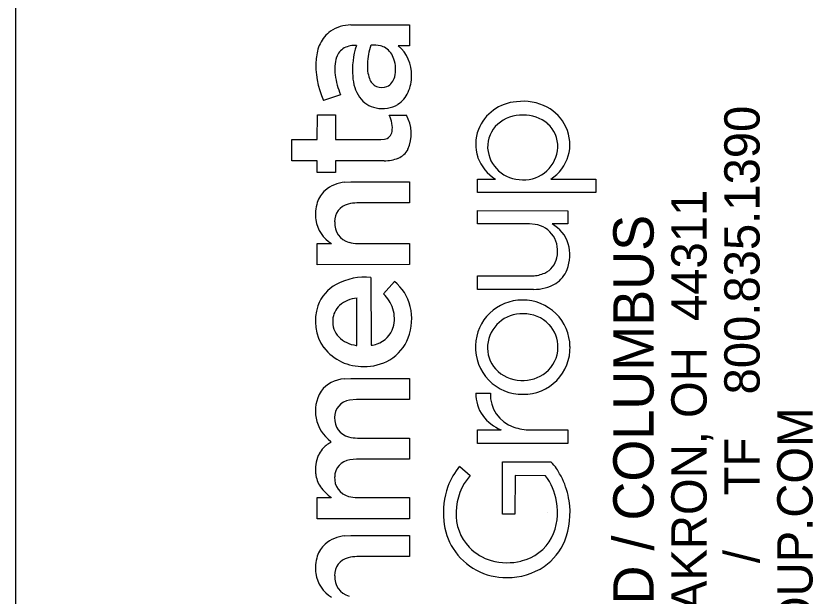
# Model space of a CAD drawing. Extents: x -6.7 to 34, y -1.6 to 22.
# Drawn here: x 32 to 33.125, y 3.882 to 4.702 of the extents above; entities that cross this region are included whole.
import ezdxf

# ---------------------------------------------------------------- set-up
doc = ezdxf.new("R2010")
doc.units = 0
doc.layers.add('SH_Border', color=7, linetype='Continuous')
doc.layers.add('SH_Data', color=7, linetype='Continuous')

msp = doc.modelspace()

# ---------------------------------------------------------------- linework, layer by layer
at = {"layer": 'SH_Border'}
msp.add_line((32, 0.5), (32, 21.5), dxfattribs=at)
at = {"layer": 'SH_Data'}
for p, q in [((32.4727, 4.689), (32.5555, 4.6892)), ((32.5555, 4.6892), (32.5557, 4.6596)), ((32.5557, 4.6596), (32.5397, 4.6596)), ((32.4582, 4.5904), (32.4343, 4.5823)), ((32.4254, 4.527), (32.4255, 4.5621)), ((32.4255, 4.5621), (32.4511, 4.5621)), ((32.4511, 4.5621), (32.4512, 4.527)), ((32.527, 4.5616), (32.5511, 4.5616)), ((32.3896, 4.4972), (32.3896, 4.527)), ((32.3896, 4.527), (32.4254, 4.527)), ((32.4512, 4.527), (32.515, 4.527)), ((32.515, 4.527), (32.52, 4.5275)), ((32.4254, 4.4972), (32.3896, 4.4972)), ((32.4254, 4.4807), (32.4254, 4.4972)), ((32.5197, 4.4972), (32.4511, 4.4972)), ((32.4511, 4.4972), (32.4511, 4.4807)), ((32.4511, 4.4807), (32.4254, 4.4807)), ((32.4644, 4.4669), (32.4729, 4.4673)), ((32.4729, 4.4673), (32.5557, 4.4673)), ((32.5557, 4.4673), (32.5557, 4.4375)), ((32.6515, 4.4521), (32.6515, 4.4711)), ((32.6515, 4.4711), (32.6771, 4.4711)), ((32.7549, 4.4713), (32.8186, 4.4711)), ((32.8186, 4.4711), (32.8184, 4.4521)), ((32.8184, 4.4521), (32.6515, 4.4521)), ((32.5557, 4.4375), (32.4814, 4.4375)), ((32.6515, 4.408), (32.6515, 4.4267)), ((32.6515, 4.4267), (32.7791, 4.4266)), ((32.7791, 4.4266), (32.7791, 4.408)), ((32.7249, 4.408), (32.6515, 4.408)), ((32.7328, 4.4073), (32.7249, 4.408)), ((32.7791, 4.408), (32.7569, 4.408)), ((32.4254, 4.3503), (32.4254, 4.3802)), ((32.4254, 4.3802), (32.4455, 4.3802)), ((32.4822, 4.3802), (32.5557, 4.3802)), ((32.5557, 4.3802), (32.5557, 4.3504)), ((32.5557, 4.3504), (32.4254, 4.3503)), ((32.5011, 4.3321), (32.5012, 4.2366)), ((32.6515, 4.3344), (32.7291, 4.3345)), ((32.6517, 4.3154), (32.6515, 4.3344)), ((32.5188, 4.3093), (32.5342, 4.3266)), ((32.7307, 4.3154), (32.6517, 4.3154)), ((32.4814, 4.2364), (32.4814, 4.303)), ((32.4802, 4.2363), (32.4814, 4.2364)), ((32.4633, 4.1891), (32.4726, 4.1897)), ((32.4726, 4.1897), (32.5556, 4.1897)), ((32.5556, 4.1897), (32.5557, 4.1598)), ((32.6493, 4.1691), (32.6698, 4.1691)), ((32.4806, 4.1598), (32.471, 4.1588)), ((32.5557, 4.1598), (32.4806, 4.1598)), ((32.6515, 4.098), (32.6515, 4.117)), ((32.6515, 4.117), (32.6848, 4.117)), ((32.726, 4.117), (32.7791, 4.117)), ((32.7791, 4.117), (32.779, 4.098)), ((32.4444, 4.0992), (32.4446, 4.1007)), ((32.4822, 4.1055), (32.5557, 4.1055)), ((32.5557, 4.1055), (32.5557, 4.0757)), ((32.779, 4.098), (32.6515, 4.098)), ((32.4809, 4.0757), (32.4714, 4.0747)), ((32.5557, 4.0757), (32.4809, 4.0757)), ((32.6264, 4.0655), (32.6411, 4.0524)), ((32.6868, 4.0718), (32.7552, 4.0719)), ((32.6868, 3.9978), (32.6868, 4.0718)), ((32.7045, 4.0524), (32.7043, 3.9978)), ((32.7474, 4.0523), (32.7045, 4.0524)), ((32.4254, 3.9915), (32.4254, 4.0214)), ((32.4254, 4.0214), (32.4451, 4.0214)), ((32.4821, 4.0214), (32.5557, 4.0214)), ((32.5557, 4.0214), (32.5557, 3.9916)), ((32.7043, 3.9978), (32.6868, 3.9978)), ((32.75, 4), (32.75, 4)), ((32.5557, 3.9916), (32.4254, 3.9915)), ((32.4644, 3.9674), (32.4729, 3.9678)), ((32.4729, 3.9678), (32.5557, 3.9678)), ((32.5557, 3.9678), (32.5557, 3.938)), ((32.5557, 3.938), (32.4814, 3.938))]:
    msp.add_line(p, q, dxfattribs=at)
for points in [[(32.4727, 4.689), (32.5555, 4.6892), (32.5557, 4.6596)], [(32.5557, 4.6596), (32.5397, 4.6596)], [(32.4582, 4.5904), (32.4343, 4.5823)], [(32.5197, 4.4972), (32.4511, 4.4972), (32.4511, 4.4807), (32.4254, 4.4807), (32.4254, 4.4972), (32.3896, 4.4972), (32.3896, 4.527), (32.4254, 4.527), (32.4255, 4.5621), (32.4511, 4.5621), (32.4512, 4.527), (32.515, 4.527), (32.52, 4.5275)], [(32.527, 4.5616), (32.5511, 4.5616)], [(32.4644, 4.4669), (32.4729, 4.4673), (32.5557, 4.4673), (32.5557, 4.4375), (32.4814, 4.4375)], [(32.7549, 4.4713), (32.8186, 4.4711), (32.8184, 4.4521), (32.6515, 4.4521)], [(32.6515, 4.4521), (32.6515, 4.4711), (32.6771, 4.4711)], [(32.7328, 4.4073), (32.7249, 4.408), (32.6515, 4.408), (32.6515, 4.4267), (32.7791, 4.4266), (32.7791, 4.408), (32.7569, 4.408)], [(32.4254, 4.3503), (32.4254, 4.3802), (32.4455, 4.3802)], [(32.4822, 4.3802), (32.5557, 4.3802), (32.5557, 4.3504), (32.4254, 4.3503)], [(32.5011, 4.3321), (32.5012, 4.2366)], [(32.7307, 4.3154), (32.6517, 4.3154), (32.6515, 4.3344), (32.7291, 4.3345)], [(32.5188, 4.3093), (32.5342, 4.3266)], [(32.4802, 4.2363), (32.4814, 4.2364), (32.4814, 4.303)], [(32.4633, 4.1891), (32.4726, 4.1897), (32.5556, 4.1897), (32.5557, 4.1598), (32.4806, 4.1598), (32.471, 4.1588)], [(32.6493, 4.1691), (32.6698, 4.1691)], [(32.6515, 4.098), (32.6515, 4.117), (32.6848, 4.117)], [(32.726, 4.117), (32.7791, 4.117), (32.779, 4.098), (32.6515, 4.098)], [(32.4444, 4.0992), (32.4446, 4.1007)], [(32.4822, 4.1055), (32.5557, 4.1055), (32.5557, 4.0757), (32.4809, 4.0757), (32.4714, 4.0747)], [(32.6264, 4.0655), (32.6411, 4.0524)], [(32.7474, 4.0523), (32.7045, 4.0524), (32.7043, 3.9978), (32.6868, 3.9978), (32.6868, 4.0718), (32.7552, 4.0719)], [(32.4254, 3.9915), (32.4254, 4.0214), (32.4451, 4.0214)], [(32.4821, 4.0214), (32.5557, 4.0214), (32.5557, 3.9916), (32.4254, 3.9915)], [(32.4644, 3.9674), (32.4729, 3.9678), (32.5557, 3.9678), (32.5557, 3.938), (32.4814, 3.938)]]:
    msp.add_lwpolyline(points, dxfattribs=at)
for centre, radius, start, end in [((32.4745, 4.6326), 0.0565, 91.8942, 122.6317), ((32.4745, 4.6326), 0.0565, 91.8942, 122.6317), ((32.4685, 4.6447), 0.043, 124.537, 155.6594), ((32.4685, 4.6447), 0.043, 124.537, 155.6594), ((32.4882, 4.6361), 0.0646, 155.9764, 175.3149), ((32.4882, 4.6361), 0.0646, 155.9764, 175.3149), ((32.4779, 4.6278), 0.0321, 85.3802, 116.6222), ((32.4779, 4.6278), 0.0321, 85.3802, 116.6222), ((32.5879, 4.6251), 0.1129, 162.0821, 184.5285), ((32.5879, 4.6251), 0.1129, 162.0821, 184.5285), ((32.5801, 4.6313), 0.0841, 159.8366, 178.0362), ((32.5801, 4.6313), 0.0841, 159.8366, 178.0362), ((32.5051, 4.6074), 0.053, 79.6696, 94.2322), ((32.5051, 4.6074), 0.053, 79.6696, 94.2322), ((32.5089, 4.6364), 0.0238, 56.8913, 76.2149), ((32.5089, 4.6364), 0.0238, 56.8913, 76.2149), ((32.5055, 4.6191), 0.0529, 358.0746, 49.762), ((32.5055, 4.6191), 0.0529, 358.0746, 49.762), ((32.4753, 4.6356), 0.024, 119.4252, 161.6629), ((32.4753, 4.6356), 0.024, 119.4252, 161.6629), ((32.5052, 4.6318), 0.0297, 17.5984, 55.7282), ((32.5052, 4.6318), 0.0297, 17.5984, 55.7282), ((32.5364, 4.6308), 0.113, 174.6101, 205.3899), ((32.5364, 4.6308), 0.113, 174.6101, 205.3899), ((32.5076, 4.6265), 0.0576, 163.1369, 188.1675), ((32.5076, 4.6265), 0.0576, 163.1369, 188.1675), ((32.4916, 4.6264), 0.0443, 345.9408, 18.9919), ((32.4916, 4.6264), 0.0443, 345.9408, 18.9919), ((32.5466, 4.6303), 0.0506, 175.5903, 199.8857), ((32.5466, 4.6303), 0.0506, 175.5903, 199.8857), ((32.5473, 4.6297), 0.0973, 186.7598, 203.7981), ((32.5473, 4.6297), 0.0973, 186.7598, 203.7981), ((32.5328, 4.6187), 0.0575, 182.5676, 213.7144), ((32.5328, 4.6187), 0.0575, 182.5676, 213.7144), ((32.5164, 4.6189), 0.0184, 198.2844, 293.3081), ((32.5164, 4.6189), 0.0184, 198.2844, 293.3081), ((32.5152, 4.6199), 0.0199, 295.2883, 347.4639), ((32.5152, 4.6199), 0.0199, 295.2883, 347.4639), ((32.5019, 4.6168), 0.0566, 336.016, 0.5951), ((32.5019, 4.6168), 0.0566, 336.016, 0.5951), ((32.5175, 4.6097), 0.0394, 303.4436, 336.18), ((32.5175, 4.6097), 0.0394, 303.4436, 336.18), ((32.5149, 4.6078), 0.0366, 215.0668, 259.8133), ((32.5149, 4.6078), 0.0366, 215.0668, 259.8133), ((32.7108, 4.5182), 0.0624, 93.9866, 158.3119), ((32.7108, 4.5182), 0.0624, 93.9866, 158.3119), ((32.7156, 4.5065), 0.0746, 62.6889, 97.0135), ((32.7156, 4.5065), 0.0746, 62.6889, 97.0135), ((32.5175, 4.6131), 0.0423, 257.5256, 300.882), ((32.5175, 4.6131), 0.0423, 257.5256, 300.882), ((32.7212, 4.5191), 0.0608, 25.0657, 61.9602), ((32.7212, 4.5191), 0.0608, 25.0657, 61.9602), ((32.4863, 4.542), 0.0452, 10.1545, 25.723), ((32.4863, 4.542), 0.0452, 10.1545, 25.723), ((32.503, 4.5351), 0.0549, 336.589, 28.8991), ((32.503, 4.5351), 0.0549, 336.589, 28.8991), ((32.7138, 4.5102), 0.0513, 87.8965, 131.1812), ((32.7138, 4.5102), 0.0513, 87.8965, 131.1812), ((32.7175, 4.5102), 0.0513, 49.9089, 92.0363), ((32.7175, 4.5102), 0.0513, 49.9089, 92.0363), ((32.4957, 4.5436), 0.0356, 351.914, 10.2059), ((32.4957, 4.5436), 0.0356, 351.914, 10.2059), ((32.7092, 4.5167), 0.0434, 132.3289, 182.0949), ((32.7092, 4.5167), 0.0434, 132.3289, 182.0949), ((32.7215, 4.5173), 0.0433, 358.0487, 47.9447), ((32.7215, 4.5173), 0.0433, 358.0487, 47.9447), ((32.5184, 4.54), 0.0126, 277.6142, 353.7918), ((32.5184, 4.54), 0.0126, 277.6142, 353.7918), ((32.707, 4.5202), 0.0581, 158.656, 198.171), ((32.707, 4.5202), 0.0581, 158.656, 198.171), ((32.7245, 4.52), 0.0574, 301.9776, 25.6418), ((32.7245, 4.52), 0.0574, 301.9776, 25.6418), ((32.5291, 4.5261), 0.0275, 292.6889, 332.0598), ((32.5291, 4.5261), 0.0275, 292.6889, 332.0598), ((32.7135, 4.5181), 0.0478, 183.5974, 271.7045), ((32.7135, 4.5181), 0.0478, 183.5974, 271.7045), ((32.7172, 4.518), 0.0477, 267.3149, 357.4019), ((32.7172, 4.518), 0.0477, 267.3149, 357.4019), ((32.5209, 4.5486), 0.0514, 268.6727, 291.5235), ((32.5209, 4.5486), 0.0514, 268.6727, 291.5235), ((32.7103, 4.5243), 0.0627, 200.8399, 238.0162), ((32.7103, 4.5243), 0.0627, 200.8399, 238.0162), ((32.4687, 4.4172), 0.0499, 94.9706, 130.2248), ((32.4687, 4.4172), 0.0499, 94.9706, 130.2248), ((32.4635, 4.4255), 0.0402, 132.2238, 161.6823), ((32.4635, 4.4255), 0.0402, 132.2238, 161.6823), ((32.4787, 4.4211), 0.056, 162.274, 187.7917), ((32.4787, 4.4211), 0.056, 162.274, 187.7917), ((32.4748, 4.4116), 0.025, 103.6868, 182.214), ((32.4748, 4.4116), 0.025, 103.6868, 182.214), ((32.4811, 4.3915), 0.046, 89.6051, 105.3303), ((32.4811, 4.3915), 0.046, 89.6051, 105.3303), ((32.4703, 4.4209), 0.0476, 188.9646, 238.6987), ((32.4703, 4.4209), 0.0476, 188.9646, 238.6987), ((32.4774, 4.4085), 0.0276, 175.5844, 255.1382), ((32.4774, 4.4085), 0.0276, 175.5844, 255.1382), ((32.7271, 4.37), 0.0377, 33.5008, 81.3295), ((32.7271, 4.37), 0.0377, 33.5008, 81.3295), ((32.7324, 4.3648), 0.0496, 17.6221, 60.3897), ((32.7324, 4.3648), 0.0496, 17.6221, 60.3897), ((32.7241, 4.3695), 0.0405, 346.5618, 31.7539), ((32.7241, 4.3695), 0.0405, 346.5618, 31.7539), ((32.4818, 4.4224), 0.0421, 254.0891, 270.5284), ((32.4818, 4.4224), 0.0421, 254.0891, 270.5284), ((32.7234, 4.3641), 0.0584, 339.162, 15.6148), ((32.7234, 4.3641), 0.0584, 339.162, 15.6148), ((32.7337, 4.3662), 0.0304, 294.6321, 348.4863), ((32.7337, 4.3662), 0.0304, 294.6321, 348.4863), ((32.739, 4.359), 0.042, 303.1039, 338.1561), ((32.739, 4.359), 0.042, 303.1039, 338.1561), ((32.4918, 4.2487), 0.0839, 83.6212, 118.2845), ((32.4918, 4.2487), 0.0839, 83.6212, 118.2845), ((32.7275, 4.3808), 0.0463, 271.952, 294.0894), ((32.7275, 4.3808), 0.0463, 271.952, 294.0894), ((32.4789, 4.2737), 0.0558, 118.8294, 160.6224), ((32.4789, 4.2737), 0.0558, 118.8294, 160.6224), ((32.494, 4.2763), 0.0644, 13.5328, 51.3627), ((32.494, 4.2763), 0.0644, 13.5328, 51.3627), ((32.7321, 4.3726), 0.0571, 268.627, 301.4778), ((32.7321, 4.3726), 0.0571, 268.627, 301.4778), ((32.4803, 4.2702), 0.0549, 19.0387, 45.4432), ((32.4803, 4.2702), 0.0549, 19.0387, 45.4432), ((32.4844, 4.2607), 0.0424, 94.0131, 130.8806), ((32.4844, 4.2607), 0.0424, 94.0131, 130.8806), ((32.7143, 4.2348), 0.0655, 89.4821, 178.7775), ((32.7143, 4.2348), 0.0655, 89.4821, 178.7775), ((32.7158, 4.2341), 0.0662, 0.4227, 90.7613), ((32.7158, 4.2341), 0.0662, 0.4227, 90.7613), ((32.487, 4.2707), 0.0644, 160.5214, 215.7815), ((32.487, 4.2707), 0.0644, 160.5214, 215.7815), ((32.477, 4.2709), 0.0298, 132.9855, 177.1802), ((32.477, 4.2709), 0.0298, 132.9855, 177.1802), ((32.4872, 4.2743), 0.047, 344.6072, 17.0067), ((32.4872, 4.2743), 0.047, 344.6072, 17.0067), ((32.4829, 4.2738), 0.0758, 339.3543, 13.3771), ((32.4829, 4.2738), 0.0758, 339.3543, 13.3771), ((32.714, 4.2324), 0.0485, 87.6883, 175.017), ((32.714, 4.2324), 0.0485, 87.6883, 175.017), ((32.7166, 4.2304), 0.0505, 44.912, 90.7591), ((32.7166, 4.2304), 0.0505, 44.912, 90.7591), ((32.4782, 4.2697), 0.0311, 175.0014, 223.2876), ((32.4782, 4.2697), 0.0311, 175.0014, 223.2876), ((32.7196, 4.2345), 0.0455, 358.3228, 43.8349), ((32.7196, 4.2345), 0.0455, 358.3228, 43.8349), ((32.499, 4.2718), 0.035, 288.0108, 343.5536), ((32.499, 4.2718), 0.035, 288.0108, 343.5536), ((32.4855, 4.2783), 0.0423, 225.0645, 262.797), ((32.4855, 4.2783), 0.0423, 225.0645, 262.797), ((32.4955, 4.2698), 0.0626, 300.9439, 338.7322), ((32.4955, 4.2698), 0.0626, 300.9439, 338.7322), ((32.4891, 4.2752), 0.0687, 217.7434, 271.6561), ((32.4891, 4.2752), 0.0687, 217.7434, 271.6561), ((32.5013, 4.2568), 0.0202, 269.7004, 294.8729), ((32.5013, 4.2568), 0.0202, 269.7004, 294.8729), ((32.7148, 4.2334), 0.0661, 177.5373, 270.9452), ((32.7148, 4.2334), 0.0661, 177.5373, 270.9452), ((32.7108, 4.2331), 0.0453, 175.5147, 221.4205), ((32.7108, 4.2331), 0.0453, 175.5147, 221.4205), ((32.7167, 4.2327), 0.0654, 269.3083, 1.6791), ((32.7167, 4.2327), 0.0654, 269.3083, 1.6791), ((32.7193, 4.2337), 0.0457, 308.9038, 359.3095), ((32.7193, 4.2337), 0.0457, 308.9038, 359.3095), ((32.492, 4.277), 0.0706, 269.2053, 300.3357), ((32.492, 4.277), 0.0706, 269.2053, 300.3357), ((32.714, 4.2373), 0.0505, 222.6626, 268.3733), ((32.714, 4.2373), 0.0505, 222.6626, 268.3733), ((32.7157, 4.2386), 0.0518, 266.5531, 308.6725), ((32.7157, 4.2386), 0.0518, 266.5531, 308.6725), ((32.4664, 4.144), 0.0452, 93.9112, 142.3072), ((32.4664, 4.144), 0.0452, 93.9112, 142.3072), ((32.4759, 4.1437), 0.0532, 148.2879, 233.9556), ((32.4759, 4.1437), 0.0532, 148.2879, 233.9556), ((32.6988, 4.1666), 0.0495, 177.1621, 216.2802), ((32.6988, 4.1666), 0.0495, 177.1621, 216.2802), ((32.7173, 4.1664), 0.0476, 176.7699, 252.1504), ((32.7173, 4.1664), 0.0476, 176.7699, 252.1504), ((32.4738, 4.135), 0.024, 96.7576, 181.6251), ((32.4738, 4.135), 0.024, 96.7576, 181.6251), ((32.4758, 4.1324), 0.026, 175.8157, 256.1672), ((32.4758, 4.1324), 0.026, 175.8157, 256.1672), ((32.7098, 4.1755), 0.0637, 216.9153, 246.8862), ((32.7098, 4.1755), 0.0637, 216.9153, 246.8862), ((32.7269, 4.1917), 0.0747, 251.1388, 269.3469), ((32.7269, 4.1917), 0.0747, 251.1388, 269.3469), ((32.4817, 4.1505), 0.045, 254.3463, 270.6103), ((32.4817, 4.1505), 0.045, 254.3463, 270.6103), ((32.4638, 4.0627), 0.0414, 117.9163, 139.243), ((32.4638, 4.0627), 0.0414, 117.9163, 139.243), ((32.4619, 4.0645), 0.0387, 139.5245, 154.847), ((32.4619, 4.0645), 0.0387, 139.5245, 154.847), ((32.4714, 4.0612), 0.0488, 156.0638, 187.3493), ((32.4714, 4.0612), 0.0488, 156.0638, 187.3493), ((32.4742, 4.0506), 0.0243, 96.5532, 179.949), ((32.4742, 4.0506), 0.0243, 96.5532, 179.949), ((32.7016, 4.0019), 0.0986, 139.7948, 159.137), ((32.7016, 4.0019), 0.0986, 139.7948, 159.137), ((32.725, 4.0394), 0.0444, 30.9891, 47.161), ((32.725, 4.0394), 0.0444, 30.9891, 47.161), ((32.6709, 4.0002), 0.1111, 25.3031, 33.9618), ((32.6709, 4.0002), 0.1111, 25.3031, 33.9618), ((32.4646, 4.0597), 0.0418, 186.5579, 213.3885), ((32.4646, 4.0597), 0.0418, 186.5579, 213.3885), ((32.4761, 4.0486), 0.0263, 175.722, 255.7863), ((32.4761, 4.0486), 0.0263, 175.722, 255.7863), ((32.699, 4.0008), 0.0775, 138.258, 179.7006), ((32.699, 4.0008), 0.0775, 138.258, 179.7006), ((32.6789, 4.001), 0.0856, 10.0751, 36.8319), ((32.6789, 4.001), 0.0856, 10.0751, 36.8319), ((32.6704, 3.9999), 0.1117, 8.8034, 25.3348), ((32.6704, 3.9999), 0.1117, 8.8034, 25.3348), ((32.4789, 4.0708), 0.0598, 214.7043, 235.6872), ((32.4789, 4.0708), 0.0598, 214.7043, 235.6872), ((32.7187, 3.9997), 0.1154, 161.1438, 185.6281), ((32.7187, 3.9997), 0.1154, 161.1438, 185.6281), ((32.4819, 4.0652), 0.0438, 253.6672, 270.1498), ((32.4819, 4.0652), 0.0438, 253.6672, 270.1498), ((32.6756, 3.9998), 0.1065, 338.2887, 9.2855), ((32.6756, 3.9998), 0.1065, 338.2887, 9.2855), ((32.6842, 4.0006), 0.0804, 333.4669, 11.0367), ((32.6842, 4.0006), 0.0804, 333.4669, 11.0367), ((32.6881, 3.9973), 0.0668, 176.6658, 223.6912), ((32.6881, 3.9973), 0.0668, 176.6658, 223.6912), ((32.6934, 3.997), 0.0899, 185.5077, 212.0129), ((32.6934, 3.997), 0.0899, 185.5077, 212.0129), ((32.4687, 3.9177), 0.0499, 94.9706, 130.2248), ((32.4687, 3.9177), 0.0499, 94.9706, 130.2248), ((32.6987, 3.9955), 0.0652, 282.8815, 331.8147), ((32.6987, 3.9955), 0.0652, 282.8815, 331.8147), ((32.4635, 3.926), 0.0402, 132.2238, 161.6823), ((32.4635, 3.926), 0.0402, 132.2238, 161.6823), ((32.6921, 3.9975), 0.0891, 212.7022, 270.714), ((32.6921, 3.9975), 0.0891, 212.7022, 270.714), ((32.6905, 4.0001), 0.0704, 224.0215, 253.88), ((32.6905, 4.0001), 0.0704, 224.0215, 253.88), ((32.6984, 3.9917), 0.0824, 305.0306, 337.6757), ((32.6984, 3.9917), 0.0824, 305.0306, 337.6757), ((32.4787, 3.9216), 0.056, 162.274, 187.7917), ((32.4787, 3.9216), 0.056, 162.274, 187.7917), ((32.4748, 3.9121), 0.025, 103.6868, 182.214), ((32.4748, 3.9121), 0.025, 103.6868, 182.214), ((32.4811, 3.892), 0.046, 89.6051, 105.3303), ((32.4811, 3.892), 0.046, 89.6051, 105.3303), ((32.6932, 4.0125), 0.0831, 254.4535, 283.9512), ((32.6932, 4.0125), 0.0831, 254.4535, 283.9512), ((32.6943, 3.9998), 0.0914, 269.3273, 304.1963), ((32.6943, 3.9998), 0.0914, 269.3273, 304.1963), ((32.4703, 3.9214), 0.0476, 188.9646, 238.6987), ((32.4703, 3.9214), 0.0476, 188.9646, 238.6987), ((32.4774, 3.909), 0.0276, 175.5844, 255.1382), ((32.4774, 3.909), 0.0276, 175.5844, 255.1382)]:
    msp.add_arc(centre, radius, start, end, dxfattribs=at)

# ---------------------------------------------------------------- texts
for s, height, p in [('800.835.1390', 0.049846, (33.0497, 4.1671)), ('450 GRANT ST., AKRON, OH  44311', 0.049846, (32.9749, 3.3374)), ('AKRON / CLEVELAND / COLUMBUS', 0.056969, (32.9001, 3.138)), ('ENVDESIGNGROUP.COM', 0.049846, (33.1244, 3.3374)), ('TF', 0.04985, (33.0497, 4.0246)), ('/  ', 0.04985, (33.0497, 3.9288))]:
    msp.add_text(s, height=height, rotation=90, dxfattribs=at).set_placement(p)

doc.saveas('drawing.dxf')
